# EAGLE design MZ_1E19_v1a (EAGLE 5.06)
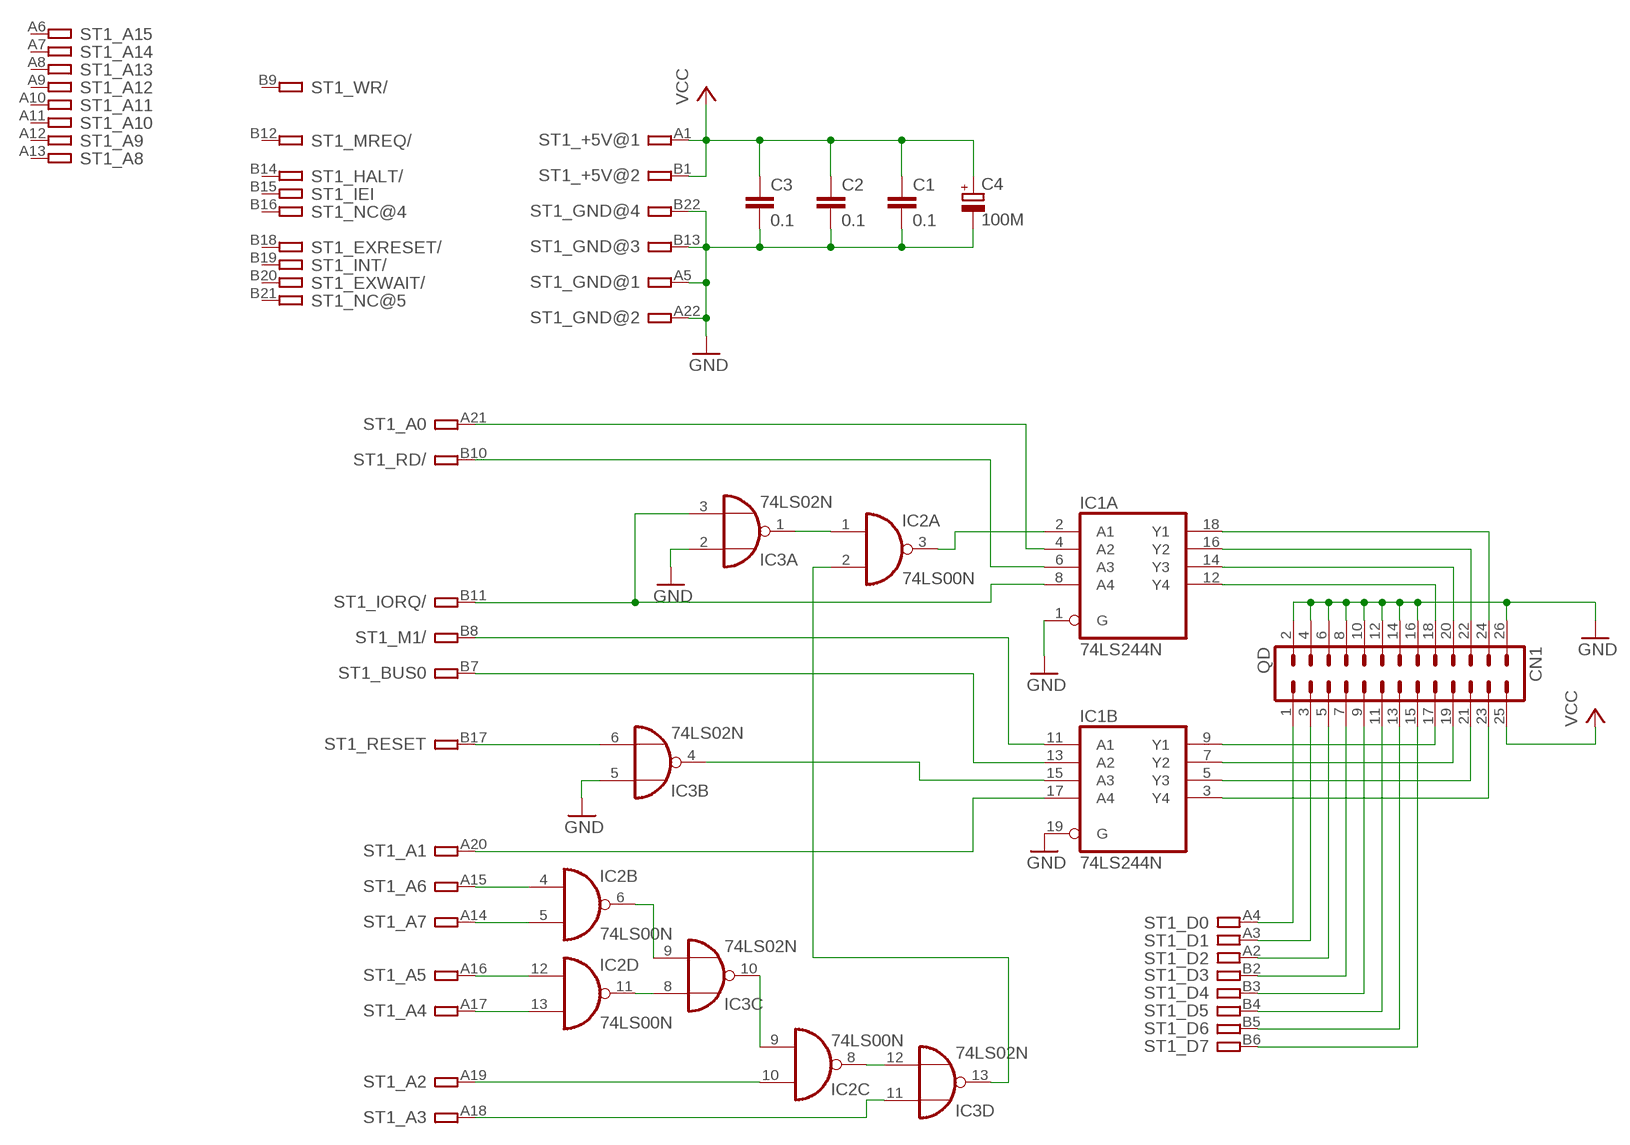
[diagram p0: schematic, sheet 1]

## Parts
C1  0.1  C-EU050-025X075  [C050-025X075]
C2  0.1  C-EU050-025X075  [C050-025X075]
C3  0.1  C-EU050-025X075  [C050-025X075]
C4  100M  CPOL-EUE3.5-8  [E3,5-8]
CN1  QD  26H  [26H]
IC1  74LS244N  [DIL20]
IC2  74LS00N  [DIL14]
IC3  74LS02N  [DIL14]
ST1  MZ800BUSSHORTN  [MZ800BUSSHORTN]

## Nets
GND [power]: C1.2 C2.2 C3.2 C4.- CN1.2 CN1.4 CN1.6 CN1.8 CN1.10 CN1.12 CN1.14 CN1.16 CN1.26 IC1.1(A:G) IC1.19(B:G) IC3.2(A:I0) IC3.5(B:I0) ST1.A5 ST1.A22 ST1.B13 ST1.B22
N$1: IC1.2(A:A1) IC2.3(A:O)
N$2: IC2.1(A:I0) IC3.1(A:O)
N$3: IC1.8(A:A4) IC3.3(A:I1) ST1.B11
N$4: IC1.6(A:A3) ST1.B10
N$5: IC1.4(A:A2) ST1.A21
N$6: IC1.11(B:A1) ST1.B8
N$7: IC1.13(B:A2) ST1.B7
N$8: IC1.15(B:A3) IC3.4(B:O)
N$9: IC3.6(B:I1) ST1.B17
N$10: IC1.17(B:A4) ST1.A20
N$11: IC2.6(B:O) IC3.9(C:I1)
N$12: IC2.11(D:O) IC3.8(C:I0)
N$13: IC2.9(C:I0) IC3.10(C:O)
N$14: IC2.8(C:O) IC3.12(D:I1)
N$15: IC2.10(C:I1) ST1.A19
N$16: IC3.11(D:I0) ST1.A18
N$17: IC2.4(B:I0) ST1.A15
N$18: IC2.5(B:I1) ST1.A14
N$19: IC2.12(D:I0) ST1.A16
N$20: IC2.13(D:I1) ST1.A17
N$21: IC2.2(A:I1) IC3.13(D:O)
N$22: CN1.20 IC1.14(A:Y3)
N$23: CN1.19 IC1.7(B:Y2)
N$24: CN1.17 IC1.9(B:Y1)
N$25: CN1.21 IC1.5(B:Y3)
N$26: CN1.18 IC1.12(A:Y4)
N$27: CN1.24 IC1.18(A:Y1)
N$28: CN1.23 IC1.3(B:Y4)
N$29: CN1.22 IC1.16(A:Y2)
N$30: CN1.1 ST1.A4
N$33: CN1.7 ST1.B2
N$34: CN1.9 ST1.B3
N$35: CN1.11 ST1.B4
N$36: CN1.13 ST1.B5
N$37: CN1.15 ST1.B6
N$42: CN1.3 ST1.A3
N$43: CN1.5 ST1.A2
VCC [power]: C1.1 C2.1 C3.1 C4.+ CN1.25 ST1.A1 ST1.B1
Unconnected: ST1.A6 ST1.A7 ST1.A8 ST1.A9 ST1.A10 ST1.A11 ST1.A12 ST1.A13 ST1.B9 ST1.B12 ST1.B14 ST1.B15 ST1.B16 ST1.B18 ST1.B19 ST1.B20 ST1.B21

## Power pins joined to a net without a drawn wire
GND: IC1.10(P:GND) IC2.7(P:GND) IC3.7(P:GND)
VCC: IC1.20(P:VCC) IC2.14(P:VCC) IC3.14(P:VCC)

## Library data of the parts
C1-C3 = resistor:C-EU: CAPACITOR, European symbol
C4 = resistor:CPOL-EU: POLARIZED CAPACITOR, European symbol
CN1 = sharp:26H: CONNECTOR
IC1 = EC_74xx-eu_MP:74*244: Octal BUFFER and LINE DRIVER, 3-state
IC2 = EC_74xx-eu_MP:74*00: Quad 2-input NAND gate
IC3 = EC_74xx-eu_MP:74*02: Quad 2-input NOR gate
ST1 = sharp:MZ800BUSSHORT: 44-bit BUS for MZ800

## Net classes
0 default: width 0.406 mm, drill 0.203 mm, clearance 0.203 mm
1 power: width 0.813 mm, drill 0.203 mm, clearance 0.203 mm to class 0, clearance 0.406 mm

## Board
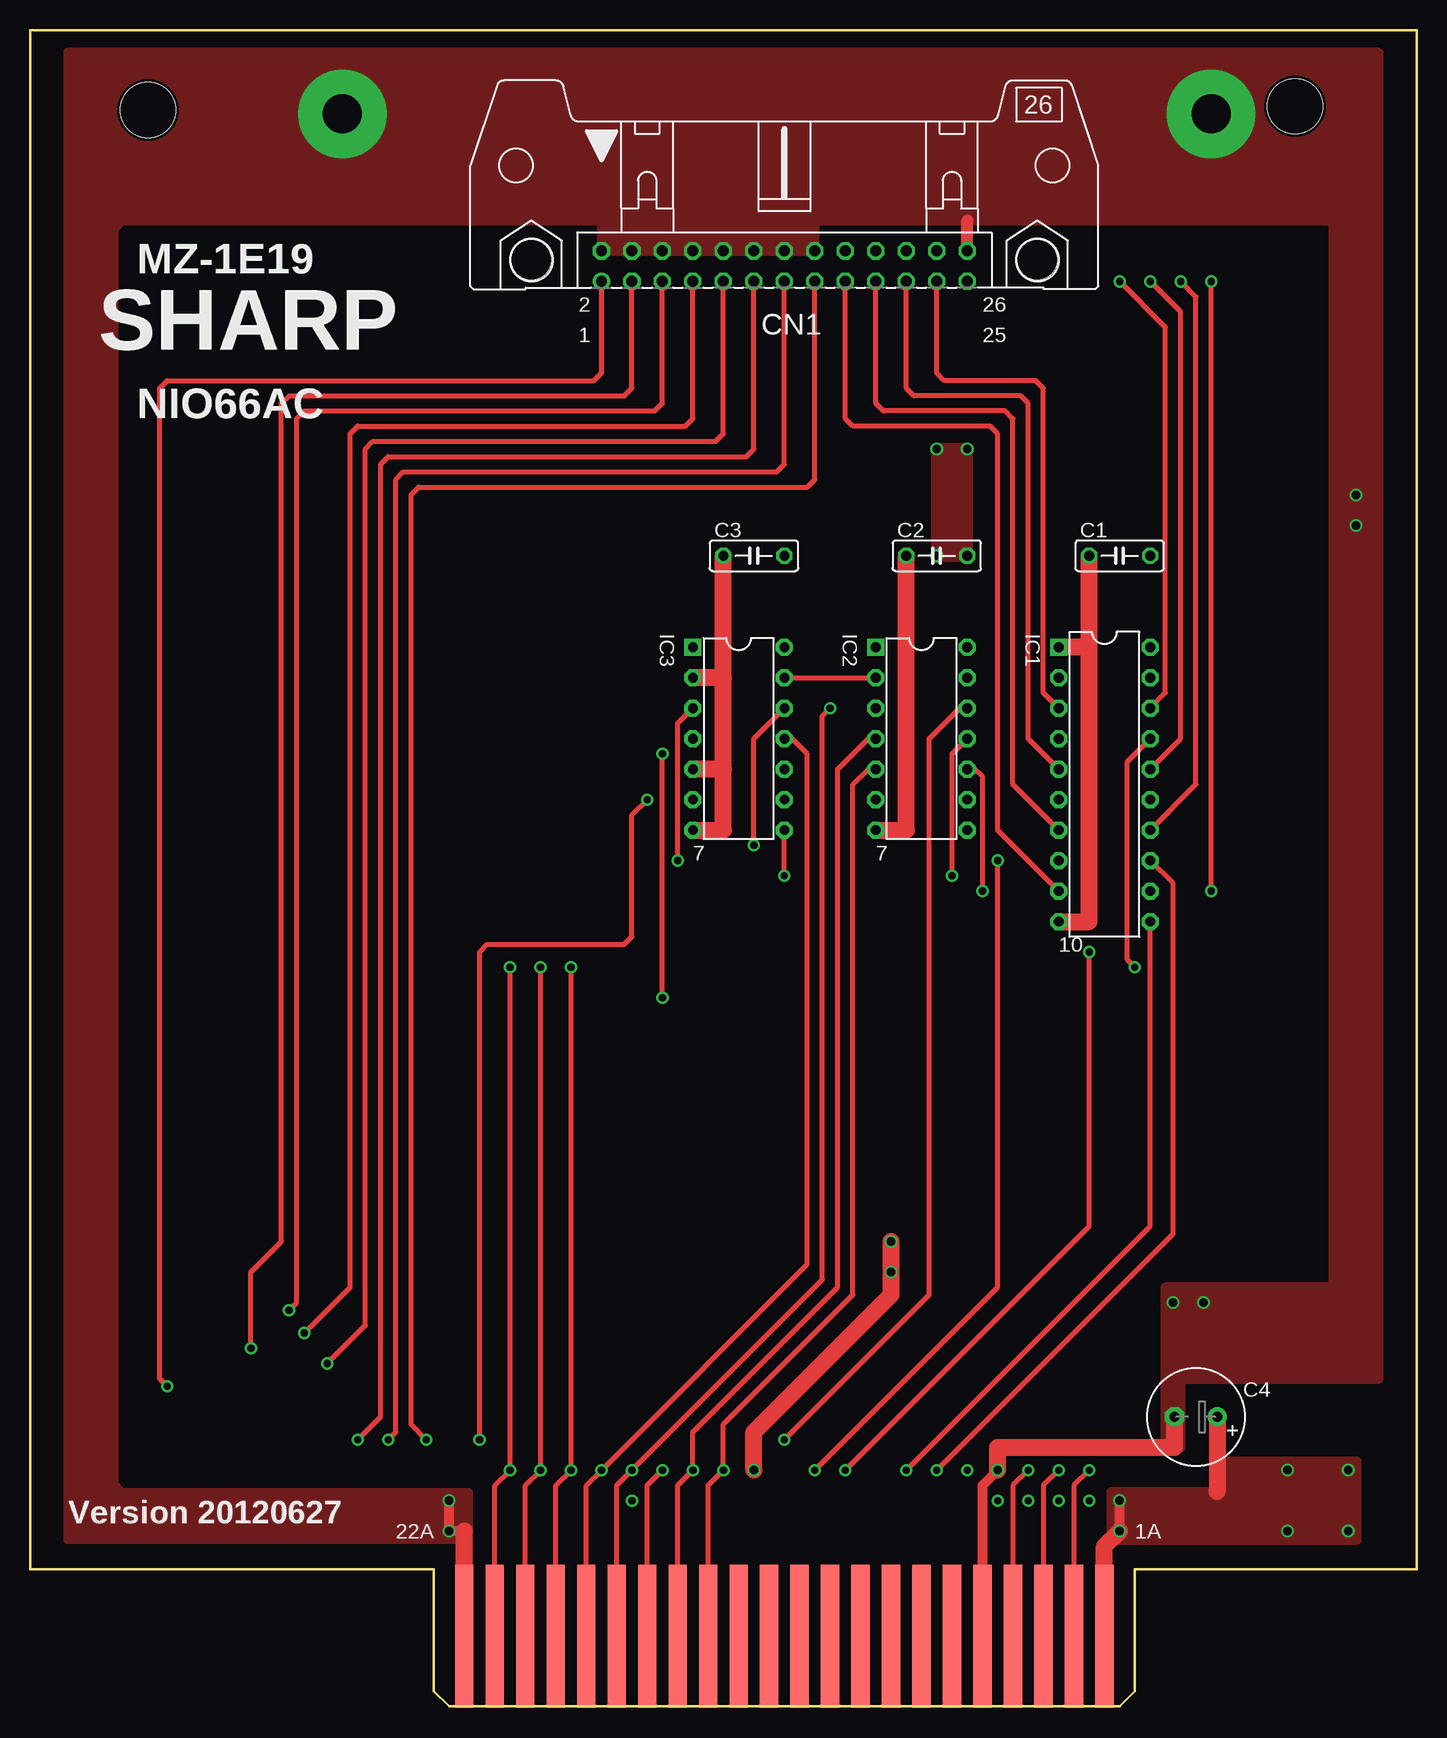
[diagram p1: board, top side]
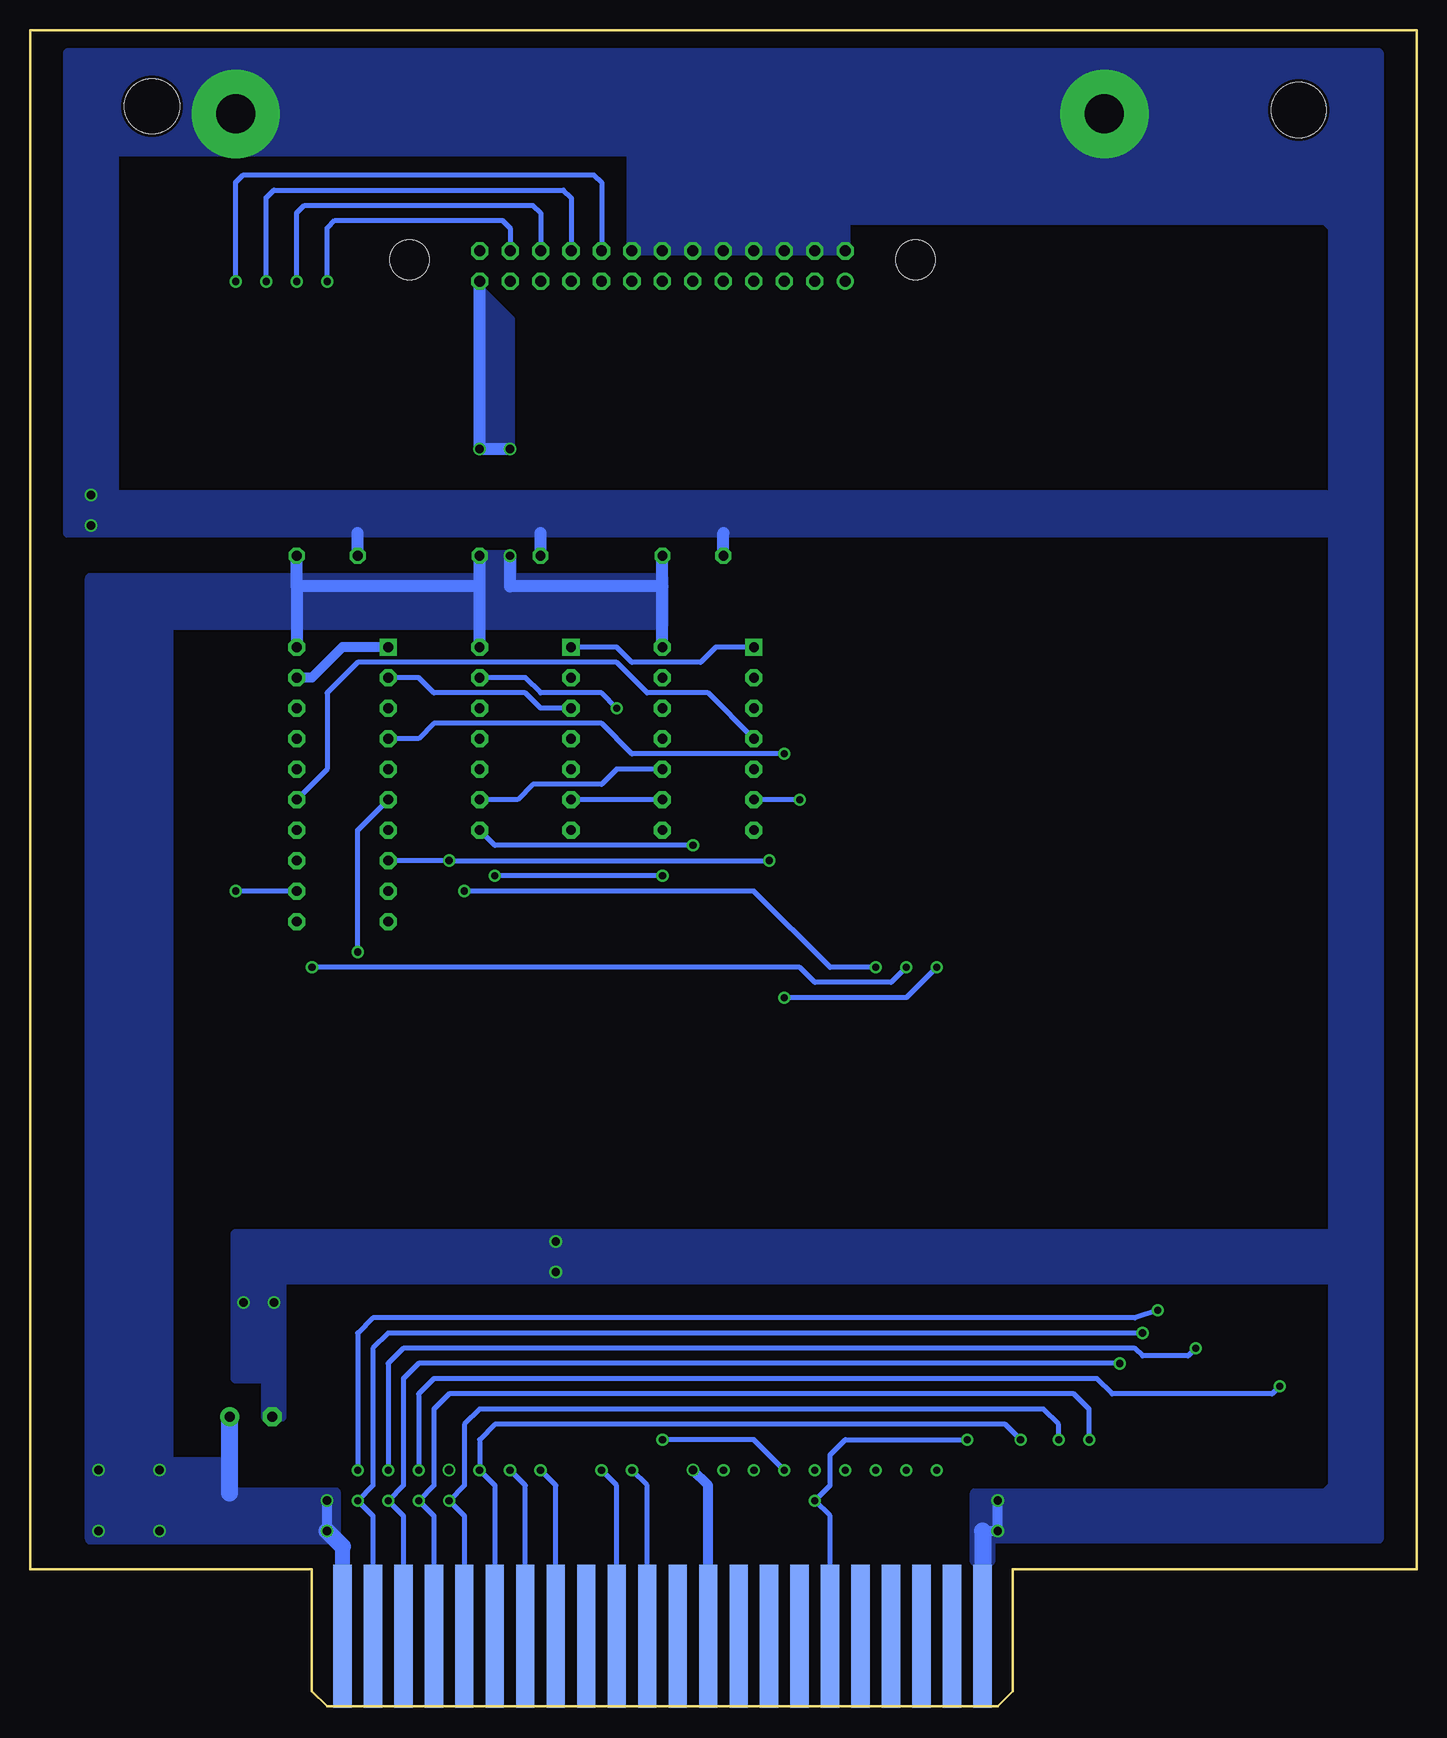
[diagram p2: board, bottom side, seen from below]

Size 115.57 x 139.7 mm. Coordinates in mm from the lower left corner, seen from the top.
Copper layers (1*16): Top 0.035mm / dielectric 1.5mm / Bottom 0.035mm
Design rules "quickdisk1": minimum track width 6mil, minimum drill 12mil, track to track 8mil, track to pad 8mil, pad to pad 8mil, via to via 8mil, smd to smd 0mil, copper to edge 10mil, drill to drill 10mil, minimum pad ring 10mil, minimum via ring 6mil, stop-mask expansion 2mil, vias tented up to drill 100mil, thermal gap 10mil
Holes 4.6 mm at 9.84,133.03 105.41,133.35

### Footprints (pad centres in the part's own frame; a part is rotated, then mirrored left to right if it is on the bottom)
C050-025X075 = drill 0.813 octagon: 1 -2.54,0; 2 2.54,0
E3,5-8 = drill 0.813 pad 1.6 round: + -1.778,0 | drill 0.813 pad 1.6 octagon: - 1.778,0
26H = drill 0.914 round: 1 -15.24,-1.27 | drill 0.914 octagon: 2 -15.24,1.27; 3 -12.7,-1.27; 4 -12.7,1.27; 5 -10.16,-1.27; 6 -10.16,1.27; 7 -7.62,-1.27; 8 -7.62,1.27; 9 -5.08,-1.27; 10 -5.08,1.27; 11 -2.54,-1.27; 12 -2.54,1.27; 13 0,-1.27; 14 0,1.27; 15 2.54,-1.27; 16 2.54,1.27; 17 5.08,-1.27; 18 5.08,1.27; 19 7.62,-1.27; 20 7.62,1.27; 21 10.16,-1.27; 22 10.16,1.27; 23 12.7,-1.27; 24 12.7,1.27; 25 15.24,-1.27; 26 15.24,1.27 | hole 3.302: -21.082,0.533; 21.082,0.533
DIL20 = drill 0.813 pad 1.422 square: 1 -11.43,-3.81 | drill 0.813 pad 1.422 octagon: 2 -8.89,-3.81; 3 -6.35,-3.81; 4 -3.81,-3.81; 5 -1.27,-3.81; 6 1.27,-3.81; 7 3.81,-3.81; 8 6.35,-3.81; 9 8.89,-3.81; 10 11.43,-3.81; 11 11.43,3.81; 12 8.89,3.81; 13 6.35,3.81; 14 3.81,3.81; 15 1.27,3.81; 16 -1.27,3.81; 17 -3.81,3.81; 18 -6.35,3.81; 19 -8.89,3.81; 20 -11.43,3.81
DIL14 = drill 0.813 pad 1.422 square: 1 -7.62,-3.81 | drill 0.813 pad 1.422 octagon: 2 -5.08,-3.81; 3 -2.54,-3.81; 4 0,-3.81; 5 2.54,-3.81; 6 5.08,-3.81; 7 7.62,-3.81; 8 7.62,3.81; 9 5.08,3.81; 10 2.54,3.81; 11 0,3.81; 12 -2.54,3.81; 13 -5.08,3.81; 14 -7.62,3.81
MZ800BUSSHORTN = smd 1.524 x 11.938: A1 64.77,-4.318; A2 62.23,-4.318; A3 59.69,-4.318; A4 57.15,-4.318; A5 54.61,-4.318; A6 52.07,-4.318; A7 49.53,-4.318; A8 46.99,-4.318; A9 44.45,-4.318; A10 41.91,-4.318; A11 39.37,-4.318; A12 36.83,-4.318; A13 34.29,-4.318; A14 31.75,-4.318; A15 29.21,-4.318; A16 26.67,-4.318; A17 24.13,-4.318; A18 21.59,-4.318; A19 19.05,-4.318; A20 16.51,-4.318; A21 13.97,-4.318; A22 11.43,-4.318 | smd 1.524 x 11.938 bottom: B1 64.77,-4.318; B2 62.23,-4.318; B3 59.69,-4.318; B4 57.15,-4.318; B5 54.61,-4.318; B6 52.07,-4.318; B7 49.53,-4.318; B8 46.99,-4.318; B9 44.45,-4.318; B10 41.91,-4.318; B11 39.37,-4.318; B12 36.83,-4.318; B13 34.29,-4.318; B14 31.75,-4.318; B15 29.21,-4.318; B16 26.67,-4.318; B17 24.13,-4.318; B18 21.59,-4.318; B19 19.05,-4.318; B20 16.51,-4.318; B21 13.97,-4.318; B22 11.43,-4.318

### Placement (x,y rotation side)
C1  90.8,95.89 180 top
C2  75.56,95.89 180 top
C3  60.33,95.89 180 top
C4  97.16,24.13 180 top
CN1  62.87,120.02 0 top
IC1  89.53,76.83 270 top
IC2  74.3,80.64 270 top
IC3  59.05,80.64 270 top
ST1  24.76,10.16 0 top
U$2  [SHARPBIGBOARDSHORT]  -0.64,0 0 top

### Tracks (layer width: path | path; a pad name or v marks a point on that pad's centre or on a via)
GND  (via drill 0.7 pad 1.02, 3.25 pad 7.37)
  Top 0.813: 36.2,14.61 v34.93,14.61 v34.93,17.14 | v80.64,19.68 79.38,18.41 ST1.A5
  Top 1.016: CN1.26 78.1,123.83
  Top 1.422: ST1.A22 36.2,14.61 | v80.64,19.68 80.64,21.59 95.38,21.59 C4.- | v60.33,19.68 60.33,22.86 71.75,34.29 v71.75,36.2 v71.75,38.73 | IC1.10 88.27,65.41 88.27,88.27 | 88.27,88.27 IC1.1 | IC2.7 73.02,73.03 C2.2 | 57.79,78.11 57.79,73.03 IC3.7 | 57.79,78.11 57.79,85.72 | 57.79,85.72 IC3.2 | 57.79,78.11 IC3.5 | 57.79,85.72 C3.2 | 88.27,88.27 C1.2
  Bottom 0.813: v34.93,17.14 v34.93,14.61 36.2,14.61 | ST1.B13 59.05,18.41 v60.33,19.68 | IC1.19 92.07,85.72 89.53,88.27 IC1.1
  Bottom 1.016: C3.2 57.79,97.79 | C2.2 73.02,97.79 | C1.2 88.27,97.79
  Bottom 1.422: 36.2,14.61 ST1.A22
  other vias: 95.25,33.66 97.79,33.66 110.49,100.97 110.49,98.42 26.04,132.72 98.42,132.72
  pour Top (no thermals): 36.51,11.43 36.51,17.78 7.62,17.78 6.99,18.41 6.99,123.19 7.62,123.83 47.62,123.83 47.62,121.28 65.41,121.28 65.41,123.83 108.58,123.83 108.58,34.92 94.61,34.92 94.61,21.59 95.88,21.59 95.88,27.3 112.39,27.3 112.39,137.79 3.17,137.79 3.17,13.97 35.88,13.97 35.88,11.43
  pour Bottom (no thermals): 3.17,137.79 3.17,13.97 35.56,13.97 35.56,12.06 36.83,12.06 36.83,17.78 7.62,17.78 6.99,18.41 6.99,35.56 94.61,35.56 94.61,24.13 95.88,24.13 95.88,27.3 98.42,27.3 98.42,39.37 6.99,39.37 6.99,123.19 7.62,123.83 47.62,123.83 47.62,121.28 65.41,121.28 65.41,129.54 108.58,129.54 108.58,100.97 7.62,100.97 7.62,97.79 112.39,97.79 112.39,137.79
N$1
  Bottom 0.406: IC2.3 73.02,83.19 74.3,84.45 81.91,84.45 83.18,85.72 IC1.2
N$2
  Bottom 0.406: IC3.1 58.42,88.27 59.69,87 65.41,87 66.67,88.27 IC2.1
N$3  (via drill 0.6 pad 1.02)
  Top 0.406: v53.98,70.48 53.98,81.92 IC3.3 | v65.41,19.68 80.64,34.92 v80.64,70.48
  Bottom 0.406: ST1.B11 64.13,18.41 v65.41,19.68 | v53.98,70.48 v80.64,70.48 IC1.8
N$4  (via drill 0.6 pad 1.02)
  Top 0.406: v88.27,62.87 88.27,40.01 v67.94,19.68
  Bottom 0.406: ST1.B10 66.67,18.41 v67.94,19.68 | IC1.6 88.27,73.03 v88.27,62.87
N$5  (via drill 0.6 pad 1.02)
  Top 0.406: ST1.A21 38.73,18.41 v40.01,19.68 v40.01,61.59 | v52.71,59.05 v52.71,79.38
  Bottom 0.406: IC1.4 83.18,80.64 81.91,81.92 67.94,81.92 65.41,79.38 v52.71,79.38 | v52.71,59.05 42.55,59.05 v40.01,61.59
N$6  (via drill 0.6 pad 1.02)
  Top 0.406: IC1.11 93.34,40.01 v73.02,19.68
  Bottom 0.406: v73.02,19.68 71.75,18.41 ST1.B8
N$7  (via drill 0.6 pad 1.02)
  Top 0.406: IC1.13 95.25,68.58 95.25,39.37 v75.56,19.68
  Bottom 0.406: v75.56,19.68 74.3,18.41 ST1.B7
N$8
  Bottom 0.406: IC3.4 59.05,84.45 64.13,84.45 66.67,87 88.27,87 90.8,84.45 90.8,78.11 IC1.15
N$9  (via drill 0.6 pad 1.02)
  Top 0.406: v51.44,75.56 50.16,74.3 50.16,64.14 49.53,63.5 38.1,63.5 37.47,62.87 v37.47,22.23
  Bottom 0.406: ST1.B17 48.9,15.88 v50.16,17.14 48.9,18.41 48.9,20.95 47.62,22.23 v37.47,22.23 | v51.44,75.56 IC3.6
N$10  (via drill 0.6 pad 1.02)
  Top 0.406: ST1.A20 41.27,18.41 v42.55,19.68 v42.55,61.59 | IC1.17 91.44,78.74 91.44,62.23 v92.07,61.59
  Bottom 0.406: v92.07,61.59 51.44,61.59 50.16,60.33 43.82,60.33 v42.55,61.59
N$11
  Bottom 0.406: IC3.9 IC2.6
N$12  (via drill 0.6 pad 1.02)
  Top 0.406: v62.87,69.22 IC3.8 | v76.83,69.22 76.83,79.38 IC2.11
  Bottom 0.406: v62.87,69.22 v76.83,69.22
N$13
  Bottom 0.406: IC3.10 66.67,78.11 67.94,76.83 73.66,76.83 74.93,75.56 IC2.9
N$14  (via drill 0.6 pad 1.02)
  Top 0.406: v60.33,71.75 60.33,80.64 IC3.12
  Bottom 0.406: IC2.8 76.83,71.75 v60.33,71.75
N$15  (via drill 0.6 pad 1.02)
  Top 0.406: ST1.A19 43.82,18.41 v45.09,19.68 v45.09,61.59 | IC2.10 78.74,78.11 79.38,77.47 v79.38,67.94
  Bottom 0.406: v45.09,61.59 48.9,61.59 55.25,67.94 v79.38,67.94
N$16  (via drill 0.6 pad 1.02)
  Top 0.406: ST1.A18 46.36,18.41 v47.62,19.68 64.77,36.83 64.77,79.38 63.5,80.64 IC3.11
N$17  (via drill 0.6 pad 1.02)
  Top 0.406: ST1.A15 53.98,18.41 v55.25,19.68 55.25,22.86 67.31,34.92 67.31,78.11 69.85,80.64 IC2.4
N$18  (via drill 0.6 pad 1.02)
  Top 0.406: ST1.A14 56.52,18.41 v57.79,19.68 57.79,23.5 68.58,34.29 68.58,76.83 69.85,78.11 IC2.5
N$19  (via drill 0.6 pad 1.02)
  Top 0.406: ST1.A16 51.44,18.41 v52.71,19.68 | IC2.12 77.47,83.19 74.93,80.64 74.93,34.29 v62.87,22.23
  Bottom 0.406: v52.71,19.68 55.25,22.23 v62.87,22.23
N$20  (via drill 0.6 pad 1.02)
  Top 0.406: ST1.A17 48.9,18.41 v50.16,19.68 66.04,35.56 66.04,82.55 v66.67,83.19
  Bottom 0.406: IC2.13 74.3,85.72 73.02,84.45 67.94,84.45 v66.67,83.19
N$21
  Top 0.406: IC3.13 IC2.2
N$22  (via drill 0.6 pad 1.02)
  Top 0.406: v95.88,118.75 97.16,117.47 97.16,76.83 IC1.14
  Bottom 0.406: CN1.20 70.48,125.73 71.12,126.36 95.25,126.36 95.88,125.73 v95.88,118.75
N$23
  Top 0.406: CN1.19 70.48,108.58 71.12,107.95 81.28,107.95 81.91,107.31 81.91,76.83 IC1.7
N$24
  Top 0.406: CN1.17 67.94,107.31 68.58,106.68 80.01,106.68 80.64,106.05 80.64,73.03 IC1.9
N$25
  Top 0.406: IC1.5 83.18,80.64 83.18,108.58 82.55,109.22 73.66,109.22 73.02,109.86 CN1.21
N$26  (via drill 0.6 pad 1.02)
  Top 0.406: v98.42,67.94 v98.42,118.75
  Bottom 0.406: CN1.18 67.94,127 68.58,127.64 97.79,127.64 98.42,127 v98.42,118.75 | IC1.12 v98.42,67.94
N$27  (via drill 0.6 pad 1.02)
  Top 0.406: v90.8,118.75 94.61,114.94 94.61,84.45 IC1.18
  Bottom 0.406: CN1.24 75.56,123.19 76.2,123.83 90.17,123.83 90.8,123.19 v90.8,118.75
N$28
  Top 0.406: IC1.3 84.45,84.45 84.45,109.86 83.82,110.49 76.2,110.49 75.56,111.12 CN1.23
N$29  (via drill 0.6 pad 1.02)
  Top 0.406: v93.34,118.75 95.88,116.2 95.88,80.64 IC1.16
  Bottom 0.406: CN1.22 73.02,124.46 73.66,125.09 92.71,125.09 93.34,124.46 v93.34,118.75
N$30  (via drill 0.6 pad 1.02)
  Top 0.406: ST1.A4 81.91,18.41 v83.18,19.68 | v11.43,26.67 10.79,27.3 10.79,109.86 11.43,110.49 46.99,110.49 47.62,111.12 CN1.1
  Bottom 0.406: v83.18,19.68 83.18,26.04 81.91,27.3 26.67,27.3 25.4,26.04 12.06,26.04 v11.43,26.67
N$33  (via drill 0.6 pad 1.02)
  Top 0.406: v22.86,31.11 26.67,34.92 26.67,106.05 27.3,106.68 54.61,106.68 55.25,107.31 CN1.7
  Bottom 0.406: ST1.B2 86.99,15.88 v88.27,17.14 86.99,18.41 86.99,29.84 85.72,31.11 v22.86,31.11
N$34  (via drill 0.6 pad 1.02)
  Top 0.406: v24.76,28.57 27.94,31.75 27.94,104.78 28.57,105.41 57.15,105.41 57.79,106.05 CN1.9
  Bottom 0.406: ST1.B3 84.45,15.88 v85.72,17.14 84.45,18.41 84.45,27.3 83.18,28.57 v24.76,28.57
N$35  (via drill 0.6 pad 1.02)
  Top 0.406: v27.3,22.23 29.21,24.13 29.21,103.5 29.84,104.14 59.69,104.14 60.33,104.78 CN1.11
  Bottom 0.406: ST1.B4 81.91,15.88 v83.18,17.14 81.91,18.41 81.91,24.77 80.64,26.04 28.57,26.04 27.3,24.77 v27.3,22.23
N$36  (via drill 0.6 pad 1.02)
  Top 0.406: v29.84,22.23 30.48,22.86 30.48,102.23 31.11,102.87 62.23,102.87 62.87,103.5 CN1.13
  Bottom 0.406: ST1.B5 79.38,15.88 v80.64,17.14 79.38,18.41 79.38,23.5 78.1,24.77 31.11,24.77 29.84,23.5 v29.84,22.23
N$37  (via drill 0.6 pad 1.02)
  Top 0.406: v33.02,22.23 31.75,23.5 31.75,100.97 32.39,101.6 64.77,101.6 65.41,102.23 CN1.15
  Bottom 0.406: ST1.B6 76.83,18.41 v78.1,19.68 78.1,22.23 76.83,23.5 34.29,23.5 v33.02,22.23
N$42  (via drill 0.6 pad 1.02)
  Top 0.406: ST1.A3 84.45,18.41 v85.72,19.68 | CN1.3 50.16,109.86 49.53,109.22 21.59,109.22 20.95,108.58 20.95,38.73 18.41,36.2 v18.41,29.84
  Bottom 0.406: v85.72,19.68 85.72,28.57 84.45,29.84 23.49,29.84 22.86,29.21 19.05,29.21 v18.41,29.84
N$43  (via drill 0.6 pad 1.02)
  Top 0.406: ST1.A2 86.99,18.41 v88.27,19.68 | v21.59,33.02 22.22,33.66 22.22,107.31 22.86,107.95 52.07,107.95 52.71,108.58 CN1.5
  Bottom 0.406: v88.27,19.68 88.27,31.11 86.99,32.38 23.49,32.38 v21.59,33.02
VCC  (via drill 0.7 pad 1.02)
  Top 0.813: v90.8,14.61 v90.8,17.14
  Top 1.016: 98.93,17.91 99.06,17.78
  Top 1.422: ST1.A1 89.53,13.34 v90.8,14.61 | C4.+ 98.93,17.91
  Bottom 0.813: v90.8,14.61 v90.8,17.14
  Bottom 1.016: IC3.14 62.87,93.34 | IC2.14 78.1,93.34 | 93.34,93.34 IC1.20 | 93.34,93.34 C1.1 | CN1.25 v78.1,104.78 v75.56,104.78 | 62.87,93.34 C3.1 | 62.87,93.34 75.56,93.34 v75.56,95.89 | 78.1,93.34 C2.1 | 78.1,93.34 93.34,93.34
  Bottom 1.27: 89.53,13.34 ST1.A1
  Bottom 1.422: v90.8,14.61 89.53,13.34 | 98.93,17.78 C4.+
  other vias: 104.77,14.61 109.85,14.61 109.85,19.68 104.77,19.68
  pour Top: 90.17,13.97 110.49,13.97 110.49,20.32 99.06,20.32 99.06,17.78 90.17,17.78
  pour Bottom (no thermals): 90.17,13.97 110.49,13.97 110.49,93.98 78.1,93.98 78.1,95.89 75.56,95.89 75.56,93.98 62.87,93.98 62.87,90.17 104.14,90.17 104.14,20.32 99.06,20.32 99.06,17.78 90.17,17.78
  pour Top (no thermals): 75.56,104.78 75.56,95.89 78.1,95.89 78.1,104.78
  pour Bottom (no thermals): 78.1,104.78 75.56,104.78 75.56,115.57 78.1,118.11

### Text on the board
tNames: MZ-1E19 | 2 | 26 | 1 | 25 | SHARP | NIO66AC | 7 | 7 | 10 | Version 20120627 | 22A | 1A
